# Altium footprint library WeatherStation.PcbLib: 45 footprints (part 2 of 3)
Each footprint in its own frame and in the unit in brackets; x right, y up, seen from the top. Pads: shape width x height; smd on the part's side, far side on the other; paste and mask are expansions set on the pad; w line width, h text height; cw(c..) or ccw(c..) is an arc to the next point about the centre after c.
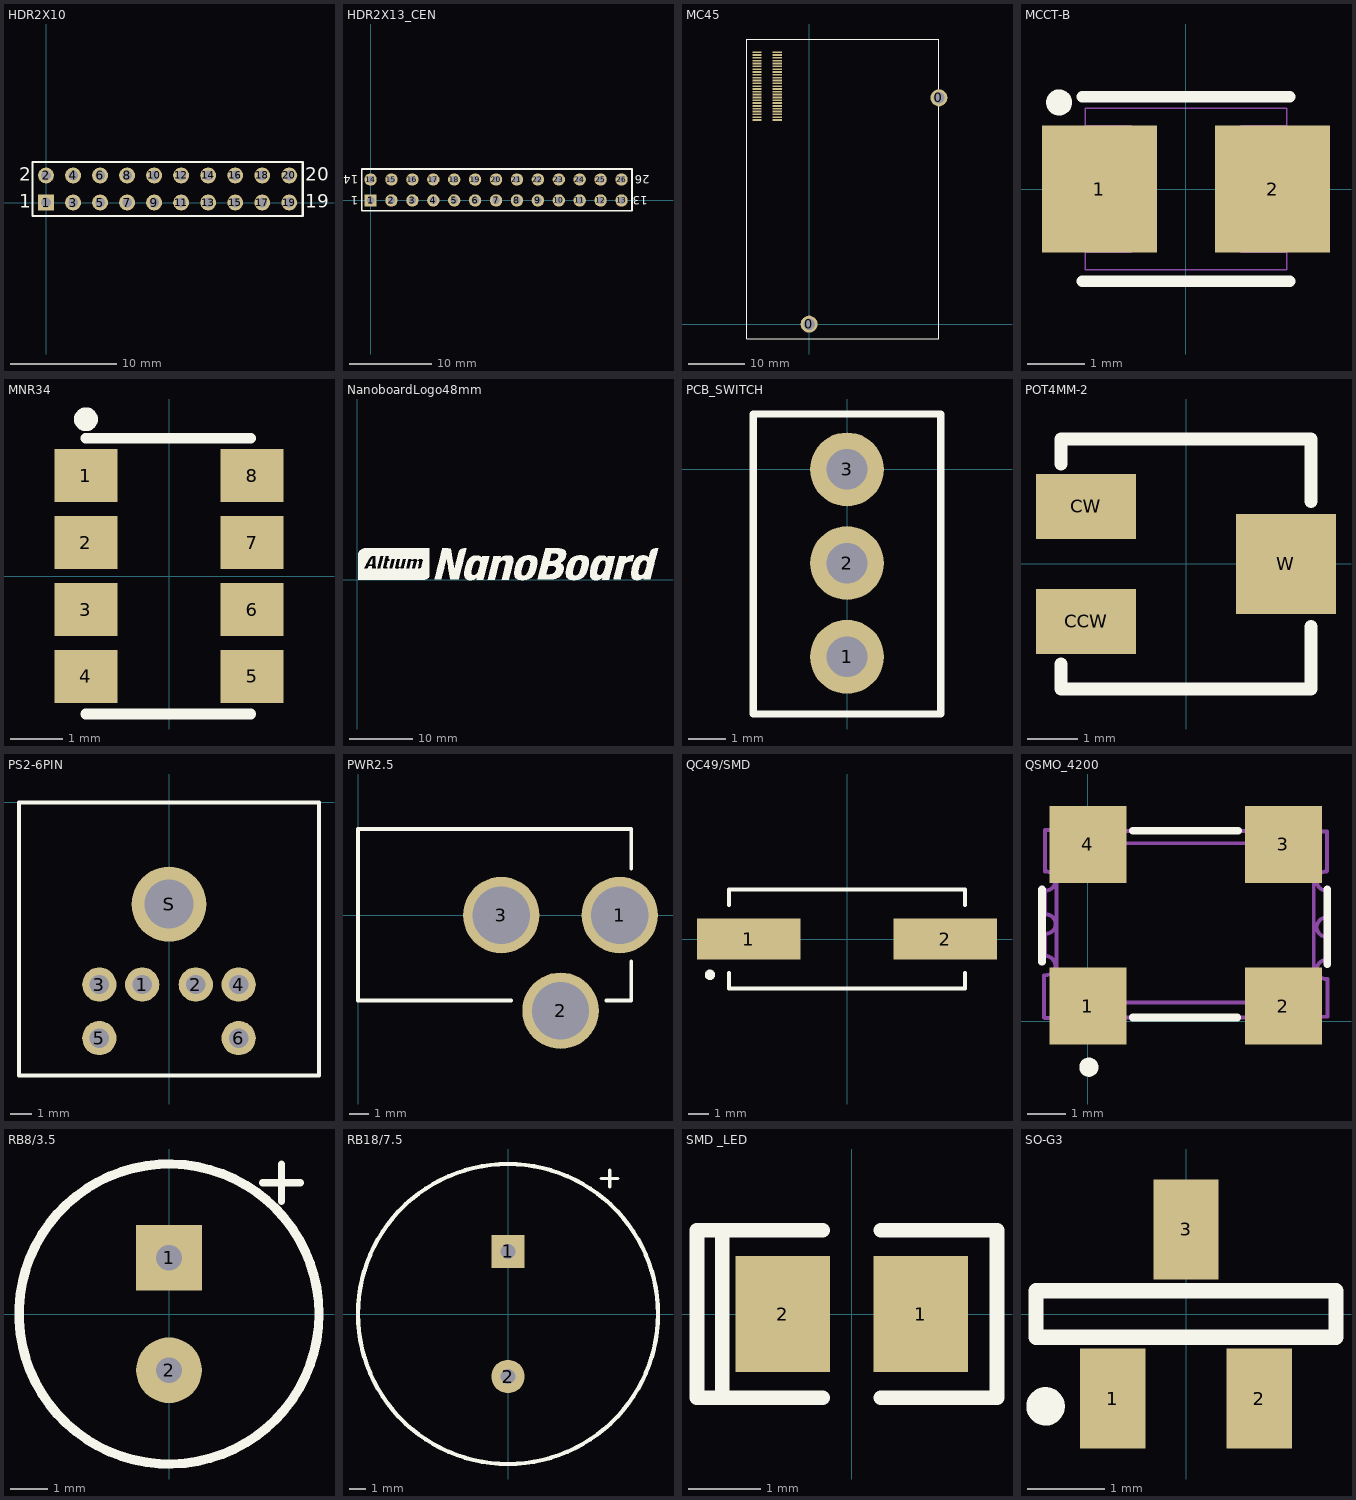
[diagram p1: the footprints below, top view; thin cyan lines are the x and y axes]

## HDR2X10 [mm]
pads (20):
  rect 1.5x1.5 hole 0.9: 1(0,0)
  round 1.5 hole 0.9: 2(0,2.54) 3(2.54,0) 4(2.54,2.54) 5(5.08,0) 6(5.08,2.54) 7(7.62,0) 8(7.62,2.54) 9(10.16,0) 10(10.16,2.54) 11(12.7,0) 12(12.7,2.54) 13(15.24,0) 14(15.24,2.54) 15(17.78,0) 16(17.78,2.54) 17(20.32,0) 18(20.32,2.54) 19(22.86,0) 20(22.86,2.54)
Top Overlay:
  lines w0.2: -1.27,-1.27 24.13,-1.27 24.13,3.81 -1.27,3.81 -1.27,-1.27
  text "2" at -2.54,2.032 h1.27
  text "1" at -2.54,-0.508 h1.27
  text "19" at 24.384,-0.508 h1.27
  text "20" at 24.384,2.032 h1.27

## HDR2X13_CEN [mm]
pads (26):
  rect 1.5x1.5 hole 0.9: 1(0,0)
  round 1.5 hole 0.9: 2(2.54,0) 3(5.08,0) 4(7.62,0) 5(10.16,0) 6(12.7,0) 7(15.24,0) 8(17.78,0) 9(20.32,0) 10(22.86,0) 11(25.4,0) 12(27.94,0) 13(30.48,0) 14(0,2.54) 15(2.54,2.54) 16(5.08,2.54) 17(7.62,2.54) 18(10.16,2.54) 19(12.7,2.54) 20(15.24,2.54) 21(17.78,2.54) 22(20.32,2.54) 23(22.86,2.54) 24(25.4,2.54) 25(27.94,2.54) 26(30.48,2.54)
Top Overlay:
  lines w0.2: -1.058,-1.27 -1.058,3.81 31.75,3.81 31.75,-1.27 -1.058,-1.27
  text "26" at 33.909,3.048 h1
  text "13" at 33.655,0.508 h1
  text "14" at -1.524,3.048 h1
  text "1" at -1.524,0.508 h1

## MC45 [mm]
pads (52):
  round 3 hole 2: 0(0,0) 0(22.95,40)
  rect 1.6x0.3 smd: 1(-5.625,48.075) 2(-5.625,47.575) 3(-5.625,47.075) 4(-5.625,46.575) 5(-5.625,46.075) 6(-5.625,45.575) 7(-5.625,45.075) 8(-5.625,44.575) 9(-5.625,44.075) 10(-5.625,43.575) 11(-5.625,43.075) 12(-5.625,42.575) 13(-5.625,42.075) 14(-5.625,41.575) 15(-5.625,41.075) 16(-5.625,40.575) 17(-5.625,40.075) 18(-5.625,39.575) 19(-5.625,39.075) 20(-5.625,38.575) 21(-5.625,38.075) 22(-5.625,37.575) 23(-5.625,37.075) 24(-5.625,36.575) 25(-5.625,36.075) 26(-9.225,36.075) 27(-9.225,36.575) 28(-9.225,37.075) 29(-9.225,37.575) 30(-9.225,38.075) 31(-9.225,38.575) 32(-9.225,39.075) 33(-9.225,39.575) 34(-9.225,40.075) 35(-9.225,40.575) 36(-9.225,41.075) 37(-9.225,41.575) 38(-9.225,42.075) 39(-9.225,42.575) 40(-9.225,43.075) 41(-9.225,43.575) 42(-9.225,44.075) 43(-9.225,44.575) 44(-9.225,45.075) 45(-9.225,45.575) 46(-9.225,46.075) 47(-9.225,46.575) 48(-9.225,47.075) 49(-9.225,47.575) 50(-9.225,48.075)
Top Overlay:
  lines w0.2: -11.05,-2.6 -11.05,50.4 22.95,50.4 22.95,-2.625 22.925,-2.6 -11.05,-2.6

## MCCT-B [mm]
pads (2):
  rect 2x2.2 smd: 1(-1.5,0) 2(1.5,0)
Top Overlay:
  circle w0.25: c-2.2,1.5 r0.1
  lines w0.2: -1.8,-1.6 1.8,-1.6 ; -1.8,1.6 1.8,1.6
Mechanical 15:
  lines w0.025: -1.75,-1.1 -0.95,-1.1 -0.95,1.1 -1.75,1.1 ; 1.75,-1.1 0.95,-1.1 0.95,1.1 1.75,1.1 ; -1.75,-1.4 1.75,-1.4 1.75,1.4 -1.75,1.4 -1.75,-1.4

## MNR34 [mm]
pads (8):
  rect 1.2x1 smd: 1(-1.575,1.905) 2(-1.575,0.635) 3(-1.575,-0.635) 4(-1.575,-1.905) 5(1.575,-1.905) 6(1.575,-0.635) 7(1.575,0.635) 8(1.575,1.905)
Top Overlay:
  circle w0.254: c-1.575,2.972 r0.1
  lines w0.2: -1.575,-2.616 1.549,-2.616 ; -1.575,2.616 1.549,2.616

## NanoboardLogo48mm [mm]
Top Overlay:
  drawing of 3446 lines, arcs and shapes, not listed

## PCB_SWITCH [mm]
pads (3):
  round 2 hole 1.1: 1(0,-5.08) 2(0,-2.54) 3(0,0)
Top Overlay:
  lines w0.2: -2.54,-6.63 2.54,-6.63 2.54,1.5 -2.54,1.5 -2.54,-6.63

## POT4MM-2 [mm]
pads (3):
  rect 2x1.3 smd: CCW(-2,-1.15) CW(-2,1.15)
  rect 2x2 smd: W(2,0)
Top Overlay:
  lines w0.254: -2.5,-2 -2.5,-2.5 2.5,-2.5 2.5,-1.25 ; -2.5,2 -2.5,2.5 2.5,2.5 2.5,1.25

## PS2-6PIN [mm]
pads (7):
  round 1.6 hole 0.9: 1(-1.25,-8.5) 2(1.25,-8.5) 3(-3.25,-8.5) 4(3.25,-8.5) 5(-3.25,-11) 6(3.25,-11)
  round 3.5 hole 2.29: S(0,-4.75)
Top Overlay:
  lines w0.2: -7,-12.75 7,-12.75 7,0 -7,0 -7,-12.75

## PWR2.5 [mm]
pads (3):
  round 4 hole 3: 1(13.7,0) 2(10.6,-5) 3(7.5,0)
Top Overlay:
  lines w0.2: 8,-4.475 0,-4.475 0,0.025 0,4.5 14.3,4.5 14.3,2.425 ; 13,-4.475 14.3,-4.475 14.3,-2.425

## QC49/SMD [mm]
pads (2):
  rect 5x2 smd: 1(-4.75,0) 2(4.75,0)
Top Overlay:
  circle w0.25: c-6.625,-1.73 r0.125
  lines w0.2: -5.7,-1.65 -5.7,-2.4 5.7,-2.4 5.7,-1.65 ; -5.7,1.65 -5.7,2.4 5.7,2.4 5.7,1.65

## QSMO_4200 [mm]
pads (4):
  rect 2x2 smd: 1(0,0.4) 2(5.08,0.4) 3(5.08,4.6) 4(0,4.6)
Top Overlay:
  circle w0.25: c0.025,-1.19 r0.125
  lines w0.2: -1.194,1.549 -1.194,3.429 ; 1.162,4.953 3.912,4.953 ; 1.168,0.102 3.886,0.102 ; 6.223,1.489 6.223,3.429
Mechanical 15:
  lines w0.1: -1.143,0.102 -1.143,1.194 ; -1.12,0.09 -0.27,0.09 -0.29,0.11 ; -1.12,3.9 -1.12,4.98 -0.26,4.98 ; -1.118,1.702 -1.118,2.286 ; -1.118,2.794 -1.118,3.378 ; -1.1,1.2 ccw(c-1.1,1.45) -1.1,1.7 ; -1.1,3.4 ccw(c-1.1,3.65) -1.1,3.9 ; -1.09,2.28 ccw(c-1.09,2.53) -1.09,2.78 ; -0.83,0.49 5.87,0.49 5.87,4.63 -0.82,4.63 -0.82,3.91 -0.82,0.51 ; -0.3,0.15 cw(c-0.05,0.15) 0.2,0.15 ; -0.23,4.91 ccw(c0.02,4.91) 0.27,4.91 ; 0.19,0.1 4.78,0.1 ; 0.25,4.95 4.87,4.95 ; 4.8,0.16 cw(c5.05,0.16) 5.3,0.16 ; 4.88,4.91 ccw(c5.13,4.91) 5.38,4.91 ; 5.29,0.12 6.23,0.12 6.23,1.1 ; 5.35,4.94 6.22,4.94 6.22,3.91 ; 6.198,1.62 6.198,2.184 ; 6.2,1.1 cw(c6.2,1.35) 6.2,1.6 ; 6.2,2.2 cw(c6.2,2.45) 6.2,2.7 ; 6.2,3.4 cw(c6.2,3.65) 6.2,3.9 ; 6.223,2.704 6.223,3.378

## RB8/3.5 [mil]
pads (2):
  rect 70x70 hole 27.56: 1(0,60)
  round 70 hole 27.56: 2(0,-60)
Top Overlay:
  circle w10: c0,0 r160
  lines w7.87: 100,140 140,140 ; 120,120 120,160

## RB18/7.5 [mm]
pads (2):
  rect 2x2 hole 0.9: 1(0,3.75)
  round 2 hole 0.9: 2(0,-3.75)
Top Overlay:
  circle w0.254: c0,0 r9
  lines w0.2: 5.588,8.128 6.604,8.128 ; 6.096,7.62 6.096,8.636

## SMD _LED [mm]
pads (2):
  rect 1.3x1.6 smd: 1(0.95,0) 2(-0.95,0)
Top Overlay:
  lines w0.2: -1.78,-1.15 -1.78,1.15 ; -0.4,-1.15 -2.13,-1.15 -2.13,1.15 -0.4,1.15 ; 0.4,-1.15 2,-1.15 2,1.15 0.4,1.15

## SO-G3 [mm]
pads (3):
  rect 0.85x1.3 smd: 1(-0.95,-1.1) 2(0.95,-1.1) 3(0,1.1)
Top Overlay:
  circle w0.25: c-1.825,-1.2 r0.125
  lines w0.2: -1.95,-0.3 -1.95,0.3 1.95,0.3 1.95,-0.3 -1.95,-0.3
